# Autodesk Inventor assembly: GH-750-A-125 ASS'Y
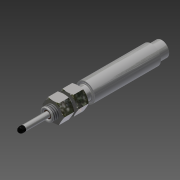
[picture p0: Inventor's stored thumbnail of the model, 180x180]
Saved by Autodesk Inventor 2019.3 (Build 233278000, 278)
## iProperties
Created: 2018-10
Part Number: GH-750-A-125 ASS'Y
Document SubType Name: Weldment
Designer: Justin
Weld Material: Stainless Steel
Mass: 51.6572 g
Surface Area: 186.876 cm^2
Volume: 17.5577 cm^3
Density: 2.94214 g/cm^3
Author: Justin
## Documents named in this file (4)
- C:\Users\Justin\Documents\CAD Drawings\The Sensor Connection\3D\LVDT\GH SERIES\GH-750-A-XXXX\GH-750-A-125\GH-750-A-125 ASS'Y.iam
- C:\Users\Justin\Documents\Inventor\Content Center Files\R2019\en-US\AS 2465(1)\AS 2465 - 1_2  UNF(1).ipt
- C:\Users\Justin\Documents\CAD Drawings\The Sensor Connection\3D\LVDT\GH SERIES\GH-750-A-XXXX\GH-750-A-125\GH-750-A-125 HOUSING_SW.ipt
- C:\Users\Justin\Documents\CAD Drawings\The Sensor Connection\3D\LVDT\GH SERIES\GH-750-A-XXXX\GH-750-A-125\GH-750-A-125 SHAFT_SW.ipt
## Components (4 placed, 3 different names)
1. AS 2465 - Inch 1/2  UNF:1 — Mate:14, Angle:3, Mate:15, Mate:18, Mate:20
2. AS 2465 - Inch 1/2  UNF:2 — Mate:14, Angle:3, Mate:15, Mate:18, Mate:19, Flush:1
3. GH-750-A-125 HOUSING_SW:1 — Mate:17, Mate:19, Flush:1, Cylindrical:1
4. GH-750-A-125 SHAFT_SW:1 — Mate:17, Cylindrical:1
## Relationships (9: Mate 6, Angle 1, Flush 1, CylindricalJoint 1)
- Mate:14: AS 2465 - Inch 1/2  UNF:1 ↔ AS 2465 - Inch 1/2  UNF:2
- Angle:3: AS 2465 - Inch 1/2  UNF:1 ↔ AS 2465 - Inch 1/2  UNF:2
- Mate:15: AS 2465 - Inch 1/2  UNF:1 ↔ AS 2465 - Inch 1/2  UNF:2
- Mate:17: GH-750-A-125 HOUSING_SW:1 ↔ GH-750-A-125 SHAFT_SW:1
- Mate:18: AS 2465 - Inch 1/2  UNF:1 ↔ AS 2465 - Inch 1/2  UNF:2
- Mate:19: AS 2465 - Inch 1/2  UNF:2 ↔ GH-750-A-125 HOUSING_SW:1
- Flush:1: AS 2465 - Inch 1/2  UNF:2 ↔ GH-750-A-125 HOUSING_SW:1
- Cylindrical:1: GH-750-A-125 HOUSING_SW:1 ↔ GH-750-A-125 SHAFT_SW:1
- Mate:20: AS 2465 - Inch 1/2  UNF:1
